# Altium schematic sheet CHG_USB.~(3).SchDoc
size A; SheetNumber: 1; SheetTotal: 1
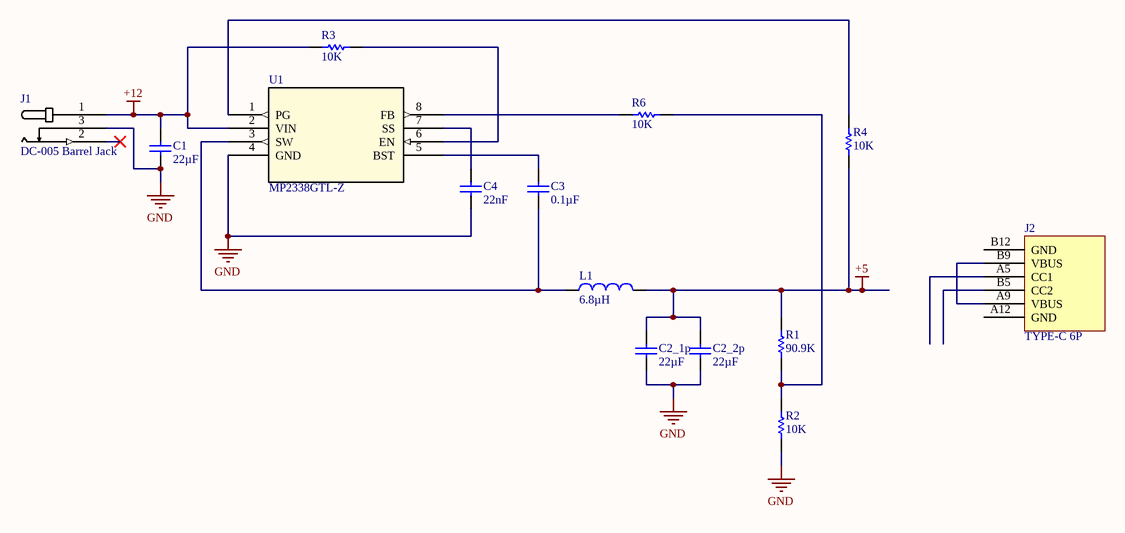
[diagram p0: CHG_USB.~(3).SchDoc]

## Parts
C1  value 22µF  (hidden comment: Capacitor)
C2_1p  value 22µF  (hidden comment: Capacitor)
C2_2p  value 22µF  (hidden comment: Capacitor)
C3  value 0.1µF  (hidden comment: Capacitor)
C4  value 22nF  (hidden comment: Capacitor)
J1  DC-005 Barrel Jack
J2  TYPE-C 6P
L1  value 6.8µH  (hidden comment: Inductor)
R1  value 90.9K  (hidden comment: Resistor)
R2  value 10K  (hidden comment: Resistor)
R3  value 10K  (hidden comment: Resistor)
R4  value 10K  (hidden comment: Resistor)
R6  value 10K  (hidden comment: Resistor)
U1  MP2338GTL-Z

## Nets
+5: C2_1p.2 C2_2p.2 L1.2 R1.2 R4.1
+12: C1.2 J1.1(VIN) R3.1 U1.2(VIN)
GND: C1.1 C2_1p.1 C2_2p.1 C4.1 J1.3(GND) R2.1 U1.4(GND)
NetC3_1: C3.1 L1.1 U1.3(SW)
NetC3_2: C3.2 U1.5(BST)
NetC4_2: C4.2 U1.7(SS)
NetJ2_A9: J2.A9(VBUS) J2.B9(VBUS)
NetR1_1: R1.1 R2.2 R6.2
NetR3_2: R3.2 U1.6(EN)
NetR4_2: R4.2 U1.1(PG)
NetR6_1: R6.1 U1.8(FB)

Not connected (* = marked no-connect by the designer): J1 2(SW)*; J2 A5(CC1) A12(GND) B5(CC2) B12(GND)

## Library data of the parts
C1 C2_1p C2_2p C3 C4 = Capacitor: SimulationGenericComponent: True
J1 = DC-005 Barrel Jack: Barrel Jack to simplify PCB complexity
L1 = Inductor: SimulationGenericComponent: True
R1-R4 R6 = Resistor: TC1: 0; SimulationGenericComponent: True
U1 = MP2338GTL-Z: MP2338 IC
